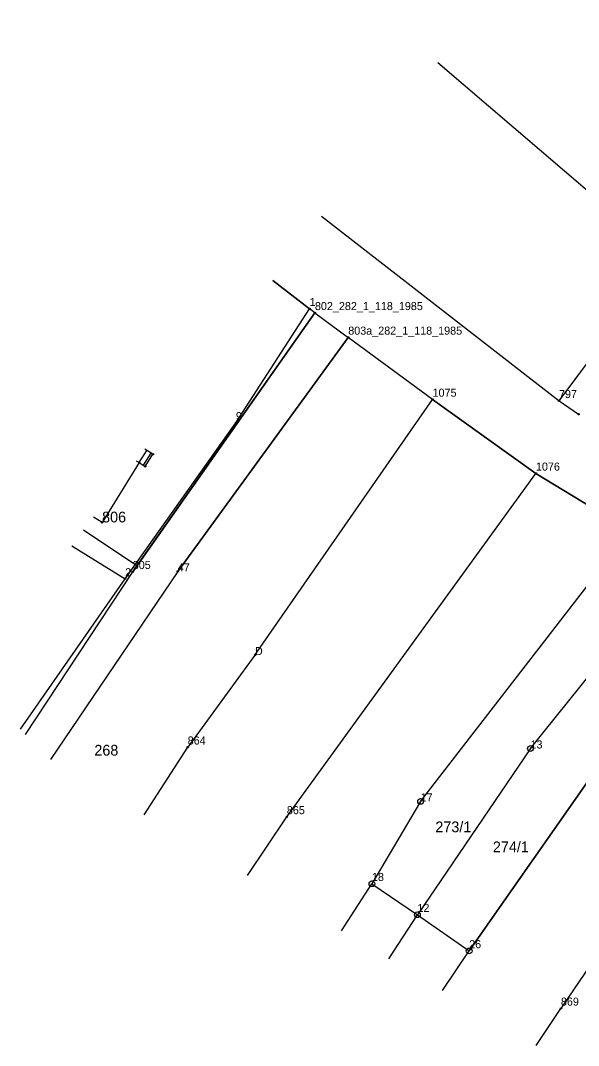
# Model space of a CAD drawing. Extents: x 7471711 to 7472261, y 5497040 to 5497544.
# Drawn here: x 7471711 to 7471788.9, y 5497396.9 to 5497539.9 of the extents above; entities that cross this region are included whole.
import ezdxf

# ---------------------------------------------------------------- set-up
doc = ezdxf.new("R2010")
doc.units = 0
for name, color, linetype in [('202-punkt graniczny', 7, 'Continuous'), ('202-punkt graniczny-Atr103', 7, 'Continuous'), ('203-punkt graniczny', 7, 'Continuous'), ('203-punkt graniczny-Atr103', 7, 'Continuous'), ('211-numer działki ewidencyjnej', 7, 'Continuous'), ('217-kontur klasyfikacyjny', 7, 'Continuous'), ('218-kontur użytku gruntowego', 7, 'Continuous'), ('219-działka ewidencyjna', 7, 'Continuous'), ('312-budynek ewidencyjny', 7, 'Continuous'), ('352-schody', 7, 'Continuous'), ('Punkt budynku', 7, 'Continuous'), ('Punkt budynku-Atr103', 7, 'Continuous')]:
    doc.layers.add(name, color=color, linetype=linetype)

# ---------------------------------------------------------------- blocks, each defined once
blk = doc.blocks.new('203')
blk.add_circle((0, 0), 0.09)
blk = doc.blocks.new('202')
blk.add_circle((0, 0), 0.4)
blk = doc.blocks.new('PUNKTBUD')
blk.add_circle((0, 0), 0.09)

msp = doc.modelspace()

# ---------------------------------------------------------------- linework, layer by layer
at = {"layer": '217-kontur klasyfikacyjny'}
for points in [[(7471801.08, 5497506.81), (7471769.24, 5497534)], [(7471753.01, 5497512.59), (7471786.16, 5497486.85)], [(7471786.16, 5497486.85), (7471801.08, 5497506.81)], [(7471751.35, 5497499.69), (7471746.22, 5497503.64)], [(7471752.09, 5497499.12), (7471751.35, 5497499.69)], [(7471726.66, 5497463.01), (7471752.09, 5497499.12)], [(7471756.74, 5497495.69), (7471732.94, 5497463.06)], [(7471768.51, 5497487.04), (7471756.74, 5497495.69)], [(7471782.94, 5497476.73), (7471768.51, 5497487.04)], [(7471796.21, 5497468.67), (7471782.94, 5497476.73)], [(7471711.69, 5497440.32), (7471726.66, 5497463.01)], [(7471732.94, 5497463.06), (7471715.18, 5497436.82)], [(7471773.62, 5497410.13), (7471800.39, 5497448.3)], [(7471769.9, 5497404.62), (7471773.62, 5497410.13)]]:
    msp.add_lwpolyline(points, dxfattribs=at)
at = {"layer": '218-kontur użytku gruntowego'}
for points in [[(7471753.01, 5497512.59), (7471786.16, 5497486.85)], [(7471786.16, 5497486.85), (7471801.08, 5497506.81)], [(7471751.35, 5497499.69), (7471746.22, 5497503.64)], [(7471752.09, 5497499.12), (7471751.35, 5497499.69)], [(7471727.24, 5497463.83), (7471752.09, 5497499.12)], [(7471756.74, 5497495.69), (7471732.94, 5497463.06)], [(7471768.51, 5497487.04), (7471756.74, 5497495.69)], [(7471782.94, 5497476.73), (7471768.51, 5497487.04)], [(7471796.21, 5497468.67), (7471782.94, 5497476.73)], [(7471727.24, 5497463.83), (7471719.8, 5497468.8)], [(7471726.66, 5497463.01), (7471727.24, 5497463.83)], [(7471711.69, 5497440.32), (7471726.66, 5497463.01)], [(7471732.94, 5497463.06), (7471715.18, 5497436.82)]]:
    msp.add_lwpolyline(points, dxfattribs=at)
at = {"layer": '219-działka ewidencyjna'}
for points in [[(7471786.16, 5497486.85), (7471825.82, 5497539.89)], [(7471753.01, 5497512.59), (7471786.16, 5497486.85)], [(7471746.22, 5497503.64), (7471751.35, 5497499.69)], [(7471741.06, 5497483.78), (7471751.35, 5497499.69)], [(7471752.09, 5497499.12), (7471751.35, 5497499.69)], [(7471752.09, 5497499.12), (7471726.66, 5497463.01)], [(7471752.09, 5497499.12), (7471756.74, 5497495.69)], [(7471732.94, 5497463.06), (7471756.74, 5497495.69)], [(7471768.51, 5497487.04), (7471756.74, 5497495.69)], [(7471743.72, 5497451.38), (7471768.51, 5497487.04)], [(7471768.51, 5497487.04), (7471782.94, 5497476.73)], [(7471786.16, 5497486.85), (7471788.9, 5497484.97)], [(7471725.6, 5497462), (7471741.06, 5497483.78)], [(7471748.17, 5497428.82), (7471782.94, 5497476.73)], [(7471782.94, 5497476.73), (7471796.21, 5497468.67)], [(7471718.17, 5497466.64), (7471725.6, 5497462)], [(7471782.18, 5497438.36), (7471803.21, 5497464.47)], [(7471711.69, 5497440.32), (7471726.66, 5497463.01)], [(7471732.94, 5497463.06), (7471715.18, 5497436.82)], [(7471710.99, 5497441.04), (7471725.6, 5497462)], [(7471766.84, 5497430.98), (7471790.22, 5497461.2)], [(7471743.72, 5497451.38), (7471734.33, 5497438.53)], [(7471800.39, 5497448.3), (7471773.62, 5497410.13)], [(7471728.25, 5497429.13), (7471734.33, 5497438.53)], [(7471782.18, 5497438.36), (7471766.4, 5497415.18)], [(7471766.84, 5497430.98), (7471760.05, 5497419.5)], [(7471742.69, 5497420.63), (7471748.17, 5497428.82)], [(7471804.31, 5497428.48), (7471786.43, 5497402.12)], [(7471755.81, 5497412.91), (7471760.05, 5497419.5)], [(7471760.05, 5497419.5), (7471766.4, 5497415.18)], [(7471762.4, 5497409.03), (7471766.4, 5497415.18)], [(7471766.4, 5497415.18), (7471773.62, 5497410.13)], [(7471769.9, 5497404.62), (7471773.62, 5497410.13)], [(7471782.95, 5497396.94), (7471786.43, 5497402.12)]]:
    msp.add_lwpolyline(points, dxfattribs=at)
at = {"layer": '312-budynek ewidencyjny'}
for points in [[(7471727.56, 5497478.23), (7471722.38, 5497469.89)], [(7471727.15, 5497478.48), (7471727.56, 5497478.23)], [(7471722.38, 5497469.89), (7471721.19, 5497470.63)]]:
    msp.add_lwpolyline(points, dxfattribs=at)
at = {"layer": '352-schody'}
for points in [[(7471727.15, 5497478.49), (7471727.56, 5497478.23), (7471728.41, 5497477.7), (7471729.47, 5497479.4), (7471728.36, 5497480.09)], [(7471727.15, 5497478.49), (7471727.56, 5497478.23), (7471728.41, 5497477.7), (7471729.47, 5497479.4), (7471728.36, 5497480.09)], [(7471727.55, 5497478.23), (7471728.61, 5497479.93)], [(7471728.15, 5497477.86), (7471729.21, 5497479.56)]]:
    msp.add_lwpolyline(points, dxfattribs=at)

# ---------------------------------------------------------------- block references
at = {"layer": '202-punkt graniczny'}
for p in [(7471782.18, 5497438.36), (7471766.84, 5497430.98), (7471760.05, 5497419.5), (7471766.4, 5497415.18), (7471773.62, 5497410.13)]:
    msp.add_blockref('202', p, dxfattribs=at)
at = {"layer": '203-punkt graniczny'}
for p in [(7471751.35, 5497499.69), (7471752.09, 5497499.12), (7471756.74, 5497495.69), (7471768.51, 5497487.04), (7471786.16, 5497486.85), (7471788.9, 5497484.97), (7471741.06, 5497483.78), (7471782.94, 5497476.73), (7471726.66, 5497463.01), (7471732.94, 5497463.06), (7471725.6, 5497462), (7471743.72, 5497451.38), (7471734.33, 5497438.53), (7471748.17, 5497428.82), (7471786.43, 5497402.12)]:
    msp.add_blockref('203', p, dxfattribs=at)
at = {"layer": 'Punkt budynku'}
for p in [(7471729.47, 5497479.4), (7471727.56, 5497478.23), (7471728.41, 5497477.7), (7471722.38, 5497469.89)]:
    msp.add_blockref('PUNKTBUD', p, dxfattribs=at)

# ---------------------------------------------------------------- texts
at = {"layer": '202-punkt graniczny-Atr103'}
for s, p in [('13', (7471782.18, 5497438.36)), ('17', (7471766.84, 5497430.98)), ('18', (7471760.05, 5497419.88)), ('12', (7471766.4, 5497415.56)), ('26', (7471773.62, 5497410.5))]:
    msp.add_text(s, height=1.125, dxfattribs=at).set_placement(p)
at = {"layer": '203-punkt graniczny-Atr103'}
for s, height, p in [('1', 1.12, (7471751.35, 5497500.07)), ('802_282_1_118_1985', 1.125, (7471752.09, 5497499.5)), ('803a_282_1_118_1985', 1.125, (7471756.74, 5497496.07)), ('1075', 1.125, (7471768.51, 5497487.42)), ('797', 1.125, (7471786.16, 5497487.23)), ('9', 1.12, (7471741.06, 5497484.16)), ('1076', 1.125, (7471782.94, 5497477.11)), ('805', 1.125, (7471726.66, 5497463.39)), ('47', 1.125, (7471732.94, 5497463.06)), ('2', 1.12, (7471725.6, 5497462.38)), ('D', 1.12, (7471743.72, 5497451.38)), ('864', 1.125, (7471734.33, 5497438.91)), ('865', 1.125, (7471748.17, 5497429.2)), ('869', 1.125, (7471786.43, 5497402.5))]:
    msp.add_text(s, height=height, dxfattribs=at).set_placement(p)
at = {"layer": '211-numer działki ewidencyjnej'}
for s, p in [('268', (7471721.3, 5497437.37)), ('273/1', (7471768.9, 5497426.68)), ('274/1', (7471776.93, 5497423.89))]:
    msp.add_text(s, height=1.5, dxfattribs=at).set_placement(p)
at = {"layer": 'Punkt budynku-Atr103'}
msp.add_text('806', height=1.5, dxfattribs=at).set_placement((7471722.38, 5497469.89))

doc.saveas('drawing.dxf')
